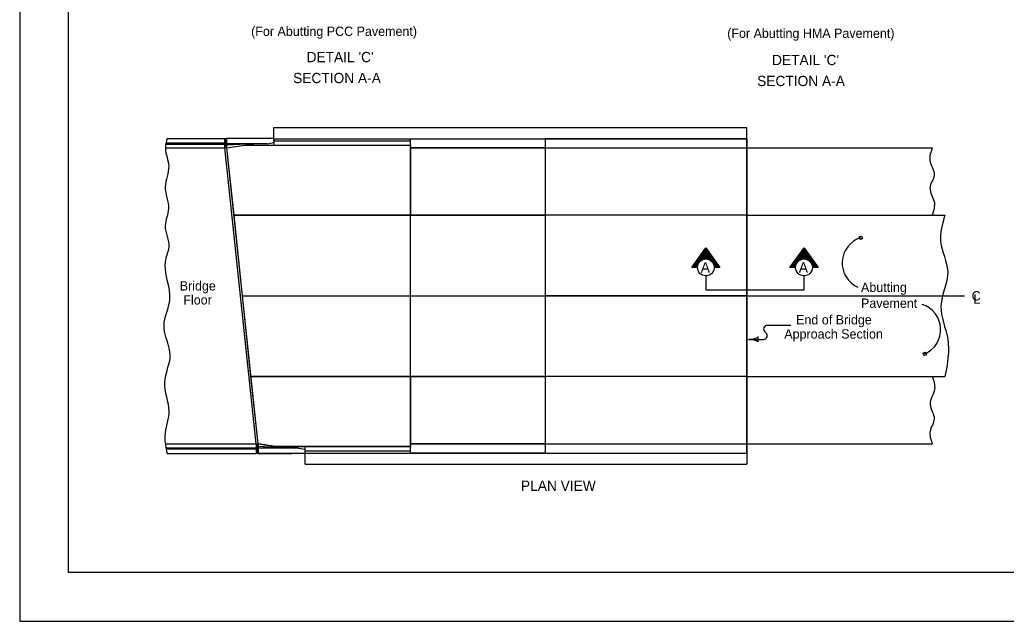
# Model space of a CAD drawing. Extents: x -2135039 to -2131695, y -2139150 to -2136566.
# Drawn here: x -2135039 to -2132926, y -2139150 to -2137862 of the extents above; entities that cross this region are included whole.
import ezdxf

# ---------------------------------------------------------------- set-up
doc = ezdxf.new("R2010")
doc.units = 0
for name, color, linetype in [('dsnCellElements', 7, 'Continuous'), ('dsnDOTLogo', 7, 'Continuous'), ('Level 1', 7, 'Continuous'), ('Level 2', 7, 'Continuous'), ('Level 3', 7, 'Continuous')]:
    doc.layers.add(name, color=color, linetype=linetype)

msp = doc.modelspace()

# ---------------------------------------------------------------- linework, layer by layer
at = {"layer": 'dsnCellElements'}
for centre in [(-2133237.6, -2138329.2), (-2133100.4, -2138577.9)]:
    msp.add_circle(centre, 3.54, dxfattribs=at)
at = {"layer": 'dsnDOTLogo'}
msp.add_lwpolyline([(-2135038.9, -2139150.4), (-2131694.9, -2139150.4), (-2131694.9, -2136566.4), (-2135038.9, -2136566.4)], close=True, dxfattribs=at)
at = {"layer": 'Level 1'}
msp.add_lwpolyline([(-2134934.4, -2137035.9), (-2131799.4, -2137035.9), (-2131799.4, -2139045.9), (-2134934.4, -2139045.9)], close=True, dxfattribs=at)
at = {"layer": 'Level 2'}
for p, q in [((-2134494.4, -2138093.1), (-2134173.1, -2138093.1)), ((-2134494.4, -2138121.9), (-2134494.4, -2138093.1)), ((-2134173.1, -2138093.1), (-2133481.9, -2138093.1)), ((-2133481.9, -2138280.9), (-2133481.9, -2138093.1)), ((-2134726.3, -2138128.5), (-2134599.5, -2138128.5)), ((-2134725.9, -2138126.1), (-2134599.5, -2138126.1)), ((-2134723.5, -2138116.5), (-2134599.5, -2138116.5)), ((-2134599.5, -2138136.9), (-2134599.5, -2138116.5)), ((-2134597.3, -2138117.4), (-2134599.5, -2138116.5)), ((-2134597.3, -2138117.4), (-2134595.2, -2138116.5)), ((-2134597.3, -2138117.4), (-2134597.3, -2138136)), ((-2134595.2, -2138136.9), (-2134595.2, -2138116.5)), ((-2134595.2, -2138136.9), (-2134595.2, -2138116.5)), ((-2134494.4, -2138116.5), (-2134595.2, -2138116.5)), ((-2134508.8, -2138127.9), (-2134595.2, -2138127.9)), ((-2134537.6, -2138127.9), (-2134595.2, -2138130.9)), ((-2134595.2, -2138136.9), (-2134537.6, -2138127.9)), ((-2134595.2, -2138136.9), (-2134556.8, -2138130.9)), ((-2134556.8, -2138130.9), (-2134201.9, -2138130.9)), ((-2134556.8, -2138130.9), (-2134201.9, -2138130.9)), ((-2134508.8, -2138127.9), (-2134494.4, -2138125.5)), ((-2134494.4, -2138116.5), (-2134494.4, -2138125.5)), ((-2134494.4, -2138117.1), (-2134201.9, -2138117.1)), ((-2134494.4, -2138121.9), (-2134201.9, -2138121.9)), ((-2134494.4, -2138125.5), (-2134494.4, -2138130.9)), ((-2134201.9, -2138398.9), (-2134201.9, -2138117.1)), ((-2134201.9, -2138117.1), (-2133481.9, -2138117.1)), ((-2134201.9, -2138130.9), (-2134201.9, -2138280.9)), ((-2133481.9, -2138117.1), (-2133913.9, -2138117.1)), ((-2133913.9, -2138117.1), (-2133913.9, -2138453.7)), ((-2133481.9, -2138440.7), (-2133481.9, -2138117.1)), ((-2134726.9, -2138136.9), (-2134599.5, -2138136.9)), ((-2134599.5, -2138136.9), (-2134597.3, -2138136)), ((-2134532.9, -2138770.5), (-2134599.5, -2138136.9)), ((-2134595.2, -2138136.9), (-2134597.3, -2138136)), ((-2134528.6, -2138770.5), (-2134595.2, -2138136.9)), ((-2134580, -2138280.9), (-2134595.2, -2138136.9)), ((-2134201.9, -2138136.9), (-2133084.4, -2138136.9)), ((-2134201.9, -2138280.9), (-2134580, -2138280.9)), ((-2134201.9, -2138280.9), (-2134580, -2138280.9)), ((-2133481.9, -2138280.9), (-2133057.3, -2138280.9)), ((-2134201.9, -2138790.3), (-2134201.9, -2138398.9)), ((-2133481.9, -2138453.7), (-2133481.9, -2138440.7)), ((-2134561.9, -2138453.7), (-2133481.9, -2138453.7)), ((-2133913.9, -2138453.7), (-2133481.9, -2138453.7)), ((-2133481.9, -2138453.7), (-2133913.9, -2138453.7)), ((-2133913.9, -2138453.7), (-2133913.9, -2138790.3)), ((-2133481.9, -2138453.7), (-2133015.5, -2138453.7)), ((-2133481.9, -2138790.3), (-2133481.9, -2138453.7)), ((-2133440.6, -2138532.8), (-2133441.9, -2138531.7)), ((-2134528.6, -2138770.5), (-2134543.7, -2138626.5)), ((-2134543.7, -2138626.5), (-2134201.9, -2138626.5)), ((-2134201.9, -2138626.5), (-2134201.9, -2138776.5)), ((-2133481.9, -2138626.5), (-2133481.9, -2138814.3)), ((-2133481.9, -2138626.5), (-2133057.3, -2138626.5)), ((-2134727.3, -2138770.5), (-2134532.9, -2138770.5)), ((-2134726.1, -2138778.9), (-2134532.9, -2138778.9)), ((-2134725.7, -2138781.3), (-2134532.9, -2138781.3)), ((-2134532.9, -2138770.5), (-2134532.9, -2138790.9)), ((-2134532.9, -2138770.5), (-2134530.7, -2138771.4)), ((-2134528.6, -2138770.5), (-2134530.7, -2138771.4)), ((-2134530.7, -2138790), (-2134530.7, -2138771.4)), ((-2134528.6, -2138770.5), (-2134528.6, -2138790.9)), ((-2134528.6, -2138770.5), (-2134528.6, -2138790.9)), ((-2134528.6, -2138770.5), (-2134471, -2138779.5)), ((-2134490.2, -2138776.5), (-2134528.6, -2138770.5)), ((-2134528.6, -2138770.5), (-2134528.6, -2138770.5)), ((-2134471, -2138779.5), (-2134528.6, -2138776.5)), ((-2134442.2, -2138779.5), (-2134528.6, -2138779.5)), ((-2134490.2, -2138776.5), (-2134201.9, -2138776.5)), ((-2134201.9, -2138776.5), (-2134490.2, -2138776.5)), ((-2134442.2, -2138779.5), (-2134427.8, -2138781.9)), ((-2134427.8, -2138781.9), (-2134427.8, -2138776.5)), ((-2134427.8, -2138790.9), (-2134427.8, -2138781.9)), ((-2134427.8, -2138785.5), (-2134201.9, -2138785.5)), ((-2134201.9, -2138770.5), (-2133084.4, -2138770.5)), ((-2134723.3, -2138790.9), (-2134532.9, -2138790.9)), ((-2134530.7, -2138790), (-2134532.9, -2138790.9)), ((-2134530.7, -2138790), (-2134528.6, -2138790.9)), ((-2134528.6, -2138790.9), (-2134455.9, -2138790.9)), ((-2134427.8, -2138790.9), (-2134528.6, -2138790.9)), ((-2134427.8, -2138790.3), (-2134201.9, -2138790.3)), ((-2134427.8, -2138814.3), (-2134427.8, -2138790.9)), ((-2134201.9, -2138790.3), (-2133481.9, -2138790.3)), ((-2133913.9, -2138790.3), (-2133481.9, -2138790.3)), ((-2134427.8, -2138814.3), (-2134173.1, -2138814.3)), ((-2134173.1, -2138814.3), (-2133481.9, -2138814.3))]:
    msp.add_line(p, q, dxfattribs=at)
for points in [[(-2133587.3, -2138392.7), (-2133599.3, -2138392.7), (-2133569.3, -2138350.7), (-2133539.3, -2138392.7), (-2133551.3, -2138392.7)], [(-2133550.1, -2138391.6), (-2133541.4, -2138391.6), (-2133569.3, -2138353), (-2133597.4, -2138391.7), (-2133588.1, -2138391.5), (-2133587.7, -2138389.8), (-2133594.4, -2138390.5), (-2133569.3, -2138355.5), (-2133543.9, -2138390.5), (-2133550.3, -2138390.1), (-2133550.6, -2138388.8), (-2133546.3, -2138388.9), (-2133569.4, -2138357.9), (-2133591.3, -2138389), (-2133587.6, -2138388.4), (-2133587.2, -2138387), (-2133588.5, -2138387.2), (-2133569, -2138360.5), (-2133548.6, -2138387.7), (-2133550.8, -2138386.3), (-2133568.9, -2138362.9), (-2133580.3, -2138377.3), (-2133578.2, -2138376.3), (-2133568.8, -2138365.3), (-2133560.6, -2138376), (-2133562.8, -2138375), (-2133568.5, -2138367.6), (-2133574.9, -2138375), (-2133572.1, -2138374.3), (-2133568.4, -2138369.5), (-2133564.6, -2138374.4), (-2133566.6, -2138374.1), (-2133568.3, -2138371.3), (-2133569.9, -2138374), (-2133568.2, -2138373.8), (-2133568.3, -2138372.9)], [(-2133377.2, -2138392.7), (-2133389.2, -2138392.7), (-2133359.2, -2138350.7), (-2133329.2, -2138392.7), (-2133341.2, -2138392.7)], [(-2133340.1, -2138391.6), (-2133331.4, -2138391.6), (-2133359.3, -2138353), (-2133387.3, -2138391.7), (-2133378.1, -2138391.5), (-2133377.6, -2138389.8), (-2133384.3, -2138390.5), (-2133359.3, -2138355.5), (-2133333.8, -2138390.5), (-2133340.2, -2138390.1), (-2133340.5, -2138388.8), (-2133336.3, -2138388.9), (-2133359.4, -2138357.9), (-2133381.3, -2138389), (-2133377.6, -2138388.4), (-2133377.2, -2138387), (-2133378.5, -2138387.2), (-2133359, -2138360.5), (-2133338.5, -2138387.7), (-2133340.8, -2138386.3), (-2133358.8, -2138362.9), (-2133370.2, -2138377.3), (-2133368.1, -2138376.3), (-2133358.7, -2138365.3), (-2133350.6, -2138376), (-2133352.7, -2138375), (-2133358.5, -2138367.6), (-2133364.9, -2138375), (-2133362.1, -2138374.3), (-2133358.4, -2138369.5), (-2133354.6, -2138374.4), (-2133356.6, -2138374.1), (-2133358.3, -2138371.3), (-2133359.9, -2138374), (-2133358.2, -2138373.8), (-2133358.3, -2138372.9)]]:
    msp.add_lwpolyline(points, dxfattribs=at)
for centre in [(-2133569.3, -2138392.7), (-2133359.2, -2138392.7)]:
    msp.add_circle(centre, 18, dxfattribs=at)
for centre, radius, start, end in [((-2133477.8, -2138503.6), 43.2, 270, 298.0725), ((-2133477.8, -2138590), 43.2, 61.9275, 90), ((-2133441.6, -2138546.8), 16.7, 162.2666, 197.7334)]:
    msp.add_arc(centre, radius, start, end, dxfattribs=at)
for points in [[(-2134723.5, -2138116.5), (-2134726.9, -2138138.1), (-2134719.8, -2138176.3), (-2134727.4, -2138220.1), (-2134720.3, -2138266.9), (-2134727.4, -2138303.5), (-2134719.8, -2138349.4), (-2134726.9, -2138376.8), (-2134718.1, -2138461.9), (-2134730.5, -2138517), (-2134717.3, -2138581.5), (-2134729, -2138639), (-2134719.6, -2138701.1), (-2134728.2, -2138754.7), (-2134723.4, -2138790.9)], [(-2133084.4, -2138136.9), (-2133089.7, -2138163.6), (-2133080.6, -2138195.2), (-2133089.4, -2138222.9), (-2133080.6, -2138251.3), (-2133084.4, -2138280.9)], [(-2133057.3, -2138280.9), (-2133066.5, -2138337.5), (-2133051.5, -2138401.8), (-2133065.9, -2138475.6), (-2133051.5, -2138545.3), (-2133057.3, -2138626.5)], [(-2133084.4, -2138626.5), (-2133079.6, -2138653.5), (-2133089, -2138686.1), (-2133080.4, -2138717), (-2133089.3, -2138743.8), (-2133084.4, -2138770.5)]]:
    msp.add_spline(points, degree=3, dxfattribs=at)
at = {"layer": 'Level 3'}
for p, q in [((-2133913.9, -2138117.1), (-2133913.9, -2138790.3)), ((-2133481.9, -2138117.1), (-2133481.9, -2138790.3)), ((-2134543.7, -2138626.5), (-2134580, -2138280.9)), ((-2134580, -2138280.9), (-2134201.9, -2138280.9)), ((-2134580, -2138280.9), (-2134201.9, -2138280.9)), ((-2134201.9, -2138280.9), (-2133913.9, -2138280.9)), ((-2133481.9, -2138280.9), (-2134201.9, -2138280.9)), ((-2133913.9, -2138280.9), (-2133913.9, -2138626.5)), ((-2133441.9, -2138531.7), (-2133443.1, -2138530.6)), ((-2133437.8, -2138516.6), (-2133387.2, -2138516.6)), ((-2133477.8, -2138546.8), (-2133445.9, -2138546.8)), ((-2134201.9, -2138626.5), (-2134543.7, -2138626.5)), ((-2134543.7, -2138626.5), (-2134201.9, -2138626.5)), ((-2133913.9, -2138626.5), (-2134201.9, -2138626.5)), ((-2133481.9, -2138626.5), (-2134201.9, -2138626.5))]:
    msp.add_line(p, q, dxfattribs=at)
for points in [[(-2134201.9, -2138136.9), (-2134201.9, -2138117.1), (-2133913.9, -2138117.1), (-2133913.9, -2138136.9)], [(-2134201.9, -2138280.9), (-2134201.9, -2138136.9), (-2133913.9, -2138136.9), (-2133913.9, -2138280.9)], [(-2133913.9, -2138770.5), (-2134201.9, -2138770.5), (-2134201.9, -2138626.5), (-2133913.9, -2138626.5)], [(-2133913.9, -2138790.3), (-2134201.9, -2138790.3), (-2134201.9, -2138770.5), (-2133913.9, -2138770.5)]]:
    msp.add_lwpolyline(points, close=True, dxfattribs=at)
for points in [[(-2133569.3, -2138410.7), (-2133569.3, -2138440.7), (-2133369.5, -2138440.7)], [(-2133370.4, -2138440.7), (-2133359.2, -2138440.7), (-2133359.2, -2138410.7)]]:
    msp.add_lwpolyline(points, dxfattribs=at)
for centre, radius, start, end in [((-2133220.6, -2138383.4), 56.8, 107.4467, 246.1375), ((-2133123.4, -2138526), 56.8, 293.8625, 72.5533), ((-2133445.9, -2138538.8), 8, 270, 48.691), ((-2133437.8, -2138524.6), 8, 90, 228.6908)]:
    msp.add_arc(centre, radius, start, end, dxfattribs=at)

# ---------------------------------------------------------------- texts
for s, height, p in [('(For Abutting PCC Pavement)', 20, (-2134543.3, -2137897.1)), ('(For Abutting HMA Pavement)', 20, (-2133523.7, -2137901.3)), ("DETAIL 'C'", 22, (-2134424.6, -2137953.3)), ("DETAIL 'C'", 22, (-2133427.7, -2137959.6)), ('SECTION A-A', 22, (-2134453.4, -2137998.2)), ('SECTION A-A', 22, (-2133459.6, -2138004.5)), ('A', 22, (-2133580.3, -2138403.7)), ('A', 22, (-2133370.3, -2138403.7)), ('Bridge', 20, (-2134696.3, -2138442.2)), ('Abutting', 20, (-2133237.1, -2138445.3)), ('C', 20, (-2133000.1, -2138463.6)), ('Floor', 20, (-2134688.5, -2138472.2)), ('Pavement', 20, (-2133237.1, -2138479.3)), ('L', 20, (-2132996.3, -2138470.5)), ('End of Bridge', 20, (-2133376.1, -2138514.8)), ('Approach Section', 20, (-2133401.4, -2138545.2)), ('PLAN VIEW', 22, (-2133965.4, -2138871.2))]:
    msp.add_text(s, height=height, dxfattribs=at).set_placement(p)

doc.saveas('drawing.dxf')
